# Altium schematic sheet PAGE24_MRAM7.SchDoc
size 381 x 381 mm; SheetNumber: 25; SheetTotal: 28
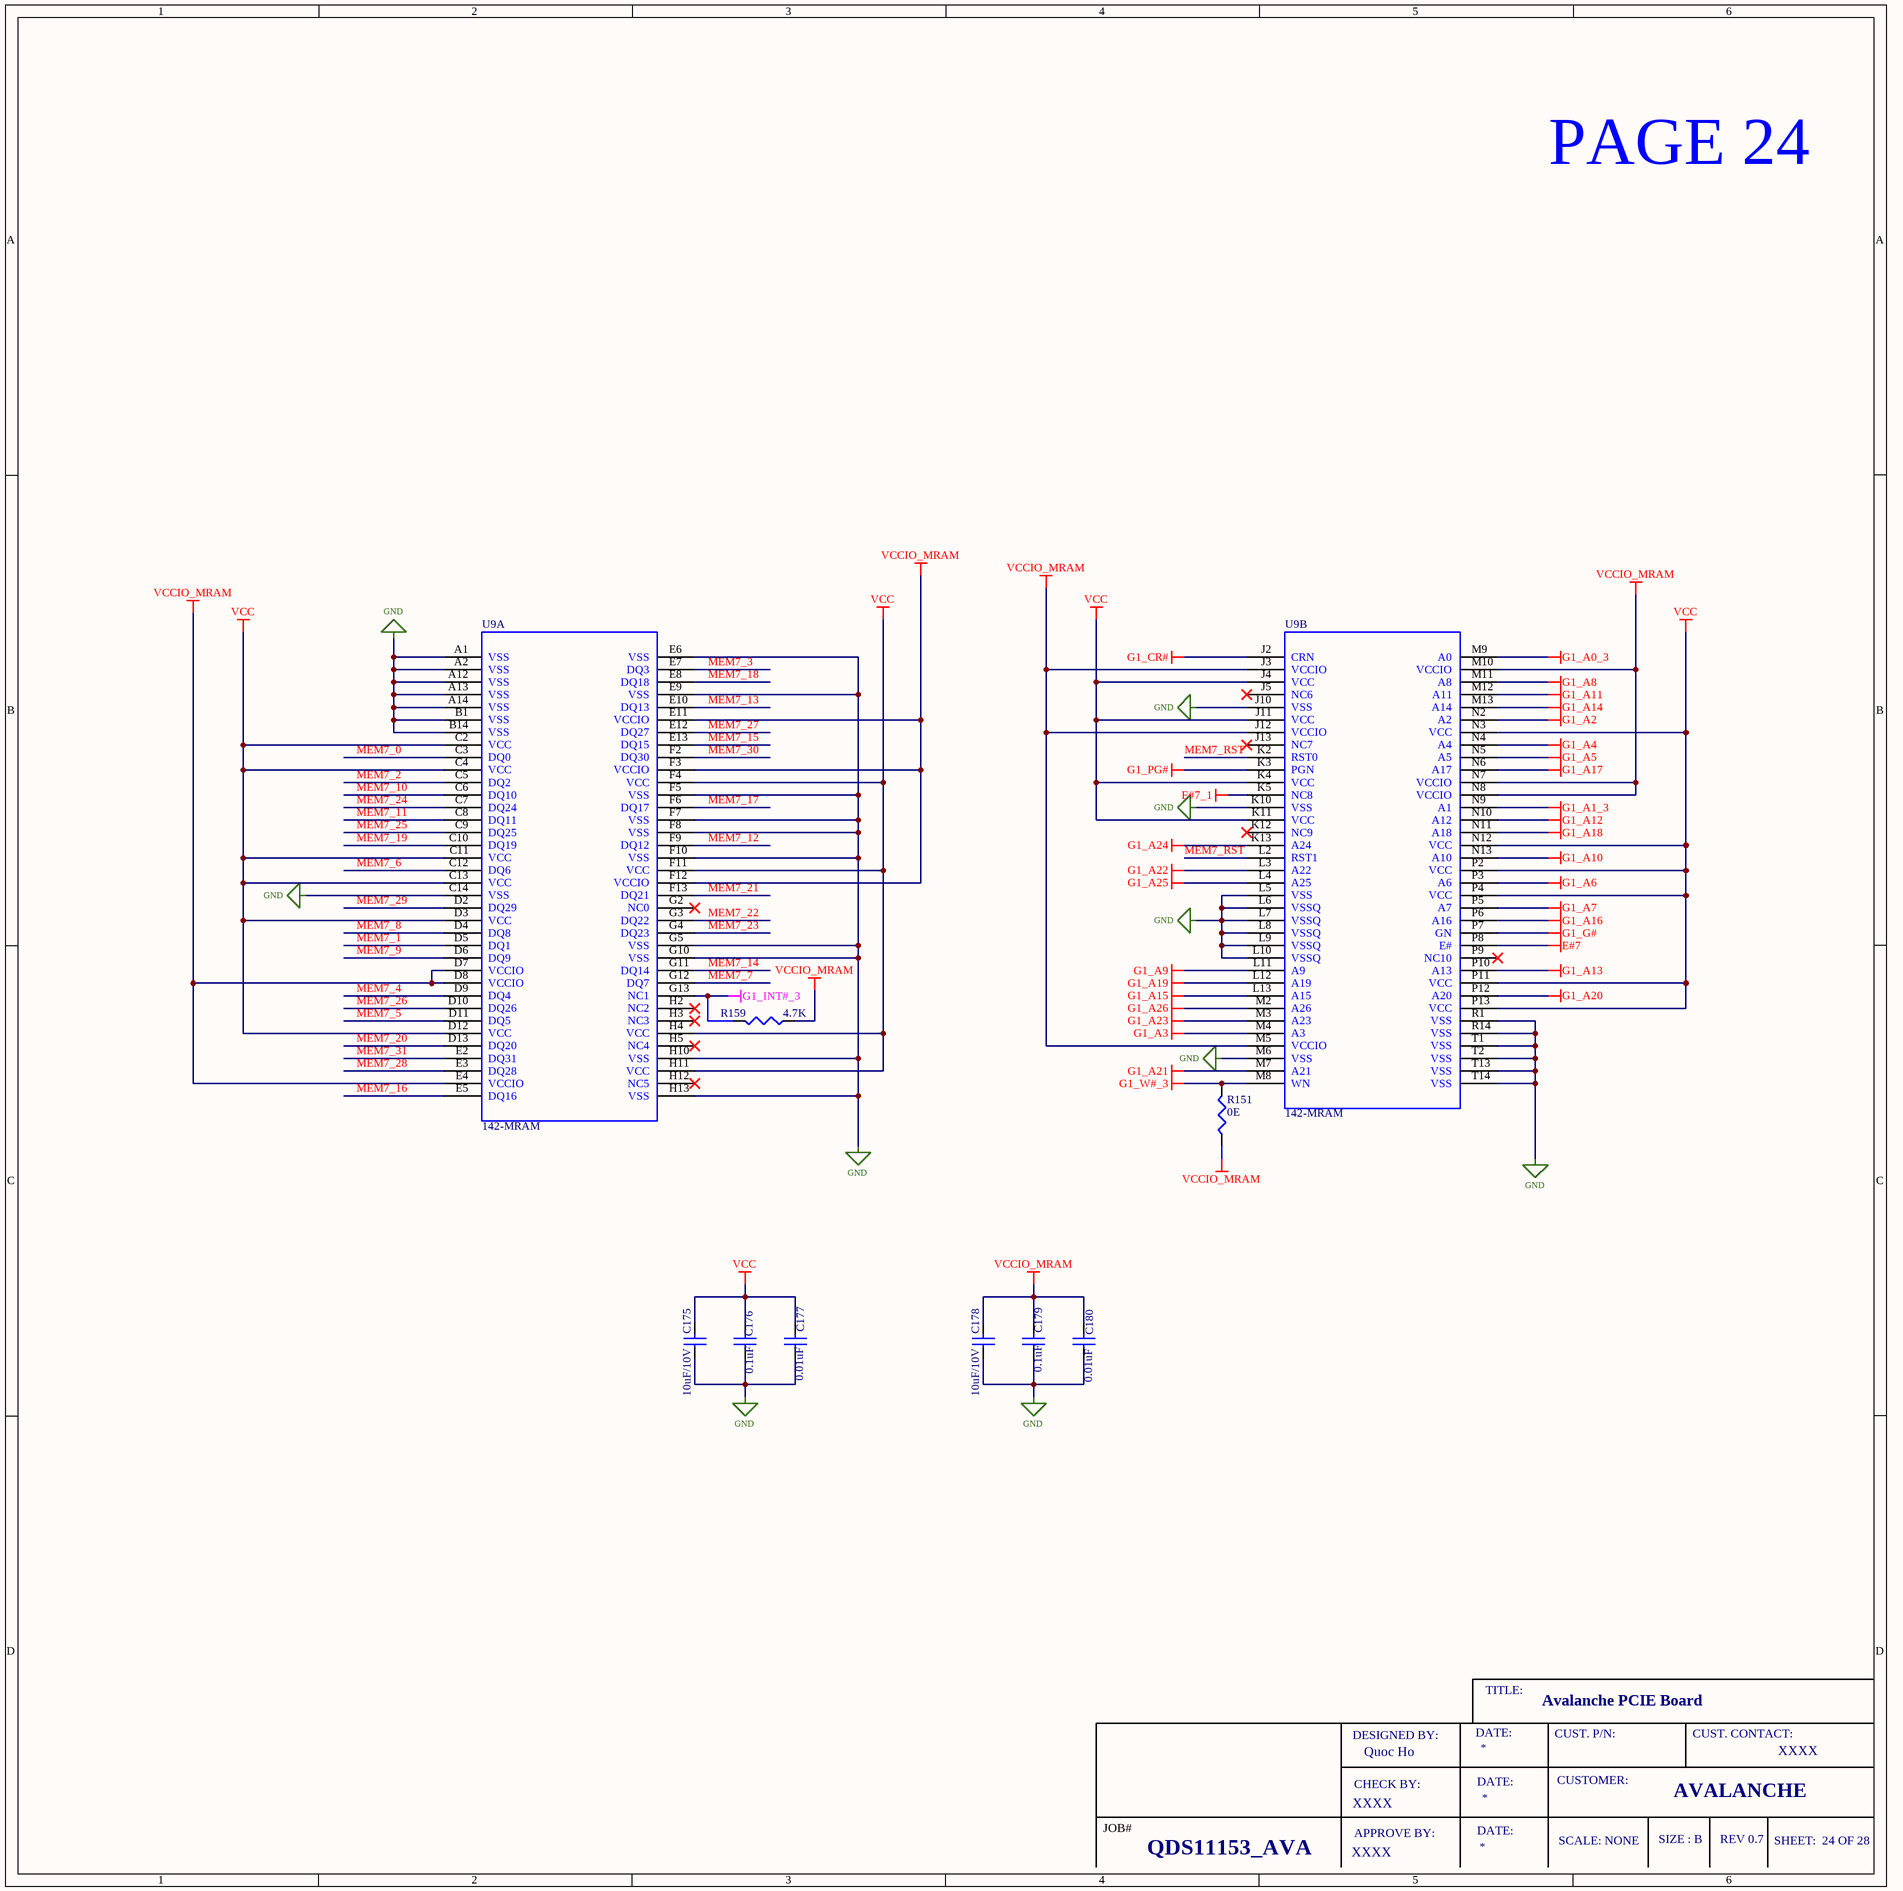
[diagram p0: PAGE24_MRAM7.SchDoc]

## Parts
C175  10uF/10V  [CN_0402]
C176  0.1uF  [CN_0402]
C177  0.01uF  [CN_0402]
C178  10uF/10V  [CN_0402]
C179  0.1uF  [CN_0402]
C180  0.01uF  [CN_0402]
R151  0E  [RN_0402]
R159  4.7K  [RN_0402]
U9  142-MRAM  [142-MRAM]  (parts A,B of 2)

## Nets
E#7: U9.P8(E#)
E#7_1: U9.K5(NC8)
G1_A0_3: U9.M9(A0)
G1_A1_3: U9.N9(A1)
G1_A2: U9.N2(A2)
G1_A3: U9.M4(A3)
G1_A4: U9.N4(A4)
G1_A5: U9.N5(A5)
G1_A6: U9.P3(A6)
G1_A7: U9.P5(A7)
G1_A8: U9.M11(A8)
G1_A9: U9.L11(A9)
G1_A10: U9.N13(A10)
G1_A11: U9.M12(A11)
G1_A12: U9.N10(A12)
G1_A13: U9.P10(A13)
G1_A14: U9.M13(A14)
G1_A15: U9.L13(A15)
G1_A16: U9.P6(A16)
G1_A17: U9.N6(A17)
G1_A18: U9.N11(A18)
G1_A19: U9.L12(A19)
G1_A20: U9.P12(A20)
G1_A21: U9.M7(A21)
G1_A22: U9.L3(A22)
G1_A23: U9.M3(A23)
G1_A24: U9.K13(A24)
G1_A25: U9.L4(A25)
G1_A26: U9.M2(A26)
G1_CR#: U9.J2(CRN)
G1_G#: U9.P7(GN)
G1_INT#_3: R159.2 U9.G13(NC1)
G1_PG#: U9.K3(PGN)
G1_W#_3: R151.2 U9.M8(WN)
GND: C175.1 C176.1 C177.1 C178.1 C179.1 C180.1 U9.A1(VSS) U9.A2(VSS) U9.A12(VSS) U9.A13(VSS) U9.A14(VSS) U9.B1(VSS) U9.B14(VSS) U9.C14(VSS) U9.E6(VSS) U9.E9(VSS) U9.F5(VSS) U9.F7(VSS) U9.F8(VSS) U9.F10(VSS) U9.G5(VSS) U9.G10(VSS) U9.H10(VSS) U9.H13(VSS) U9.J10(VSS) U9.K10(VSS) U9.L5(VSS) U9.L6(VSSQ) U9.L7(VSSQ) U9.L8(VSSQ) U9.L9(VSSQ) U9.L10(VSSQ) U9.M6(VSS) U9.R1(VSS) U9.R14(VSS) U9.T1(VSS) U9.T2(VSS) U9.T13(VSS) U9.T14(VSS)
VCC: C175.2 C176.2 C177.2 U9.C2(VCC) U9.C4(VCC) U9.C11(VCC) U9.C13(VCC) U9.D3(VCC) U9.D12(VCC) U9.F4(VCC) U9.F11(VCC) U9.H4(VCC) U9.H11(VCC) U9.J4(VCC) U9.J11(VCC) U9.K4(VCC) U9.K11(VCC) U9.N3(VCC) U9.N12(VCC) U9.P2(VCC) U9.P4(VCC) U9.P11(VCC) U9.P13(VCC)
VCCIO_MRAM: C178.2 C179.2 C180.2 R151.1 R159.1 U9.D7(VCCIO) U9.D8(VCCIO) U9.E4(VCCIO) U9.E11(VCCIO) U9.F3(VCCIO) U9.F12(VCCIO) U9.J3(VCCIO) U9.J12(VCCIO) U9.M5(VCCIO) U9.M10(VCCIO) U9.N7(VCCIO) U9.N8(VCCIO)
MEM7_0: U9.C3(DQ0)
MEM7_1: U9.D5(DQ1)
MEM7_2: U9.C5(DQ2)
MEM7_3: U9.E7(DQ3)
MEM7_4: U9.D9(DQ4)
MEM7_5: U9.D11(DQ5)
MEM7_6: U9.C12(DQ6)
MEM7_7: U9.G12(DQ7)
MEM7_8: U9.D4(DQ8)
MEM7_9: U9.D6(DQ9)
MEM7_10: U9.C6(DQ10)
MEM7_11: U9.C8(DQ11)
MEM7_12: U9.F9(DQ12)
MEM7_13: U9.E10(DQ13)
MEM7_14: U9.G11(DQ14)
MEM7_15: U9.E13(DQ15)
MEM7_16: U9.E5(DQ16)
MEM7_17: U9.F6(DQ17)
MEM7_18: U9.E8(DQ18)
MEM7_19: U9.C10(DQ19)
MEM7_20: U9.D13(DQ20)
MEM7_21: U9.F13(DQ21)
MEM7_22: U9.G3(DQ22)
MEM7_23: U9.G4(DQ23)
MEM7_24: U9.C7(DQ24)
MEM7_25: U9.C9(DQ25)
MEM7_26: U9.D10(DQ26)
MEM7_27: U9.E12(DQ27)
MEM7_28: U9.E3(DQ28)
MEM7_29: U9.D2(DQ29)
MEM7_30: U9.F2(DQ30)
MEM7_31: U9.E2(DQ31)
MEM7_RST: U9.K2(RST0) U9.L2(RST1)

Not connected (* = marked no-connect by the designer): U9 G2(NC0)* H2(NC2)* H3(NC3)* H5(NC4)* H12(NC5)* J5(NC6)* J13(NC7)* K12(NC9)* P9(NC10)*

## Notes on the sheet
- PAGE 24
- TITLE:
- Avalanche PCIE Board
- DESIGNED BY:
- CHECK BY:
- Quoc Ho
- DATE:
- CUST. P/N:
- CUSTOMER:
- CUST. CONTACT:
- XXXX
- JOB#
- APPROVE BY:
- SCALE: NONE
- SIZE : B
- AVALANCHE
- REV 0.7
- SHEET:  24 OF 28
- QDS11153_AVA

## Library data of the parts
C175 C178 = CAP: CAP CER 10UF 10V X5R 0402; Manufacturer Part Number: GRM155R61A106ME11D; Manufacturer: Murata Electronics
C176 C179 = CAP: CAP CER 0.1UF 50V X7R 0402; Manufacturer: Murata Electronics; Manufacturer Part Number: GCM155R71H104KE02J
C177 C180 = CAP: 0.01 µF, 25 V, 0402 [1005 Metric], ± 10%, X7R; Manufacturer Part Number: CC0402JRX7R8BB103; Manufacturer: YAGEO
R151 = RES: RES 0 OHM JUMPER 1/16W 0402; Manufacturer Part Number: RC0402FR-070RL_DNI; Manufacturer: YAGEO
R159 = RES: RES 4.7K OHM 1% 1/16W 0402; Manufacturer Part Number: RC0402FR-134K7L; Manufacturer: YAGEO
U9 = 142-MRAM: IC 142-MRAM MEMORY; Manufacturer: Avalanche Technology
